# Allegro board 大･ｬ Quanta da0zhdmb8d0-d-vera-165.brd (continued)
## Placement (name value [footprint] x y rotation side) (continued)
TP278  *  [TP2050]  93.24 49.11 180 bottom
TP279  *  [TP2050]  127.83 40.72 180 bottom
TP280  *  [TP2050]  129.1 40.72 180 bottom
TP281  *  [TP2050]  130.95 40.72 180 bottom
TP282  *  [TP2050]  130.95 41.99 180 bottom
TP285  *  [TP2050]  89.76 39.28 180 bottom
TP286  *  [TP2050]  85.55 44.16 0 top
TP287  *  [TP2050]  85.12 46.72 0 top
U1  NAU88L25  [QFN32-5X5-5-33P-0_85H]  23.21 15.02 0 top
U3  MAX98357AETE+T*  [QFN16-3X3-5-17P-0_8H]  37.77 20.47 180 top
U4  AZC099-04S.R7G  [SOT23-6-2_8-95-6P]  12.26 67.29 0 top
U5  MAX98357AETE+T*  [QFN16-3X3-5-17P-0_8H]  32.64 20.5 180 top
U6  AZ1065-06F.R7G  [DFN10-4_1X2-8-11P]  17.62 29.24 270 bottom
U8  G5245AT11U  [SOT23-5-2_8-95-5P-G708]  43.4 55.41 90 top
U23  *RClamp0524P  [SON10-2_5X1-5-SMT]  16.15 43.06 90 bottom
U26  PS8203  [TQFN32-3X6-4-41P-0_8H]  21.1 44.97 90 top
U80  SKL_ULT  [BGA1356-INTEL-SKYLAKE-U]  123.83 57.1 90 bottom
U82  SLB9670  [QFN32-5X5-5-33P-SLB9645VQ]  58.92 57.77 270 top
U83  SLG4R41084  [QFN12-1_6X1_6-4]  150.36 21.49 180 top
U86  TPS22965  [SON8-2X2-5-9P]  174.97 23.53 0 top
U90  PI3USB9281CXWE  [QFN20-3X4-5-21P-0_55H]  21.94 68.36 0 top
U95  STM32F051CBU6TR  [QFN48-7X7-5-49P-0_65H]  34.14 49.59 180 top
U96  PI3USB30532  [QFN40-3X6-4-41P]  21.98 62.78 270 bottom
U97  AP21510FM-7  [DFN2018-6-1_8X2-5-7P]  17.75 58.27 0 top
U98  AP21510FM-7  [DFN2018-6-1_8X2-5-7P]  17.75 55.79 0 top
U108  *SN74LVC1G08DCKR  [SC70-2_1-65-5P]  23.46 20.73 180 bottom
U111  SN74LVC1G08DCKR  [SOT353-1-2_125-65-5P]  47.08 55.28 0 bottom
U123  74LVC1G74GT  [SON8-1_95X1-5]  85.82 25.56 90 bottom
U124  PJT7600  [SOT363-2_1-65-6P]  15.03 55.13 270 bottom
U126  PJT7600  [SOT363-2_1-65-6P]  14.88 54.9 270 top
U130  PJT7600  [SOT363-2_1-65-6P]  42 45.88 180 top
U132  *G923-330T1UF  [SOT23-5]  24.27 27.41 180 top
U133  TPD4E101DPWR  [SON4-0_8X0_8-48-5P-0_4H]  12.79 64.55 0 bottom
U135  SN74AHC1G08DCKR  [SOT353-1-2_125-65-5P]  95.47 89.57 0 top
U138  SN74LVC125APWR  [TSSOP14-6_4-65-TXB0104PWR]  94.32 78.28 180 top
UAP1008  SN74LVC1G08DCKR  [SOT353-1-2_125-65-5P]  71.32 57.31 180 top
UAP1012  W25Q128FVSIG_128Mb/16MB  [SOIC8-7_9-1_27-2_16H]  76.29 56.29 270 bottom
UCP4006  TMP432ADGSR  [TSSOP10-4_9-5]  90.74 17.04 270 bottom
UCP4007  *TMP431BDGKR  [MSOP8-4_9-65]  82.14 16.62 90 bottom
UCP4034  ESD_TPD4E05U06DQAR  [SON10-2_5X1-5-0_55H]  16.2 65.18 180 top
UCP4036  ESD_TPD4E05U06DQAR  [SON10-2_5X1-5-0_55H]  10.38 70.52 270 top
UPM3253  SPI_FLASH  [SOIC8-7_9-1_27]  94.33 30.89 90 bottom
USM2000  LPDDR3_SS_8G#1  [BGA178-SAMSUNG-K4E8E304EE]  168.58 74.11 0 bottom
USM2001  LPDDR3_SS_8G#1  [BGA178-SAMSUNG-K4E8E304EE]  152.33 85.34 0 bottom
USM2002  DC@LPDDR3_SS_8G#1  [BGA178-SAMSUNG-K4E8E304EE]  129.77 87.49 0 bottom
USM2003  DC@LPDDR3_SS_8G#1  [BGA178-SAMSUNG-K4E8E304EE]  111.04 87.49 0 bottom
USM2006  SDIN9DW4_16G  [BGA153-SANDISK-SDIN7DP4-16G]  59.93 48.33 180 bottom
X5  24MHz,30ppm  [XTL-3_2X2_5-2_2X1_6-0_9H]  123.66 35.64 0 bottom
X6  32.768KHz,20ppm  [XTL-3_2X1_5-2_5-0_8H]  105.5 78.11 0 bottom
X8  32.768KHz,20ppm  [XTL-3_2X1_5-2_5-0_8H]  78.96 51.09 180 top

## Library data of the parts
C1 C1C4 C1C7 C1C28 C1C29 C1C41-C1C45 C1C47 C1C48 C1C50 C1D8 C1D17 C1M4-C1M9 C1P4-C1P7 C2 C2B3 C2M1-C2M5 C3 C4 C7L11-C7L15 C8L3 C8L6 C8L7 C8L9 C8L11 C8L13-C8L20 C32 C35 C43 C51 C62-C65 C67 C72 C129-C133 C135-C137 C139 C141 C151 C153 C186 C187 C289 C291 C340 C341 C343 C344 C386 C437 C590 C783 C785 C789-C791 C827 C828 C831 C832 C842 C843 C849 C850 C867 C868 C870-C873 C887 C888 C893 C946-C948 C952 C968 C981-C984 C1009 C1024-C1033 C1080 C1087-C1089 C1102-C1107 C1109-C1116 C1136-C1142 C6001-C6005 CAP1020 CAP1022 CAP1024 CAP1073 CAP1079 CAP1101-CAP1103 CAP1108-CAP1110 CAP1115-CAP1117 CAP1122-CAP1124 CAP1129-CAP1131 CAP1136-CAP1138 CAP1141 CAP1142 CAP1147 CAP1148 CAP1150 CAP1152 CAP1155-CAP1157 CAP1159 CAP1161 CAP1162 CAP1164-CAP1169 CAP1171-CAP1174 CAP1176-CAP1179 CAP1181 CAP1183 CAP1184 CAP1186 CAP1187 CAP1189 CAP1191-CAP1194 CAP1196 CAP1197 CAP1199 CAP1201 CAP1203 CAP1204 CAP1206-CAP1208 CAP1210 CAP1211 CAP1213-CAP1215 CAP1217 CAP1218 CAP1220 CAP1221 CAP1223 CAP1224 CAP1226 CAP1227 CAP1229 CAP1231 CAP1232 CAP1234-CAP1236 CAP1240-CAP1245 CAP1247-CAP1250 CAP1252-CAP1262 CAP1264 CAP1265 CAP1267 CAP1268 CAP1270-CAP1272 CAP1274-CAP1313 CAP1316-CAP1321 CAP1422-CAP1439 CAP1441-CAP1452 CAP1456-CAP1465 CAP1467-CAP1495 CAP1498-CAP1500 CAP14466 CAP14472-CAP14483 CAP14490 CAP14491 CAP14493 CCP4019 CCP4089 CCP4090 CCP4092-CCP4094 CCP4156 CCP4157 CCP4166-CCP4169 CCP4195 CCP4196 CCP4198 CCP4215 CCP4216 CPM3428 CPM3432-CPM3440 CPM3479 CPM4346 CPM4429 CPM4431 CSM1017-CSM1030 CSM2029-CSM2043 CSM2097-CSM2111 CSM2129-CSM2131 CSM2133-CSM2142 CSM2156-CSM2160 CSM3132 EC2 EC3 PC1-PC3 PC8 PC9 PC12 PC14-PC27 PC46 PC301-PC310 PC1051 PC1142-PC1144 PC1146-PC1328 PC9091 PC9093-PC9123 = CAP NON-POL_BGM
CCP4197 PC4-PC7 PC10 PC11 PC9124 = CAP POL_BGM
CN2 JCP4056 = FFCFPC_30P_BGM
CN3 = FFCFPC_8P_BGM
CN4 J1P2 = FFCFPC_4P_BGM
CN8 = NGFF_79P_EKEY_FT_BGM
CN12 = HDMI_19P_BGM
CN17 = HOUSING_50P_2R_BGM
CPM4189 CPM4192 F2B1 F100 F104 JP3546 JP5076 JP5100 PR3-PR5 PR8 PR12-PR15 PR19 PR20 PR22 PR71-PR89 PR91-PR138 PR142-PR161 PR164-PR188 PR190 R1A1 R1A2 R1A4PD1 R1B26-R1B28 R1B30 R1B32 R1B33 R1C10 R1D4 R1D7 R1D9 R1D10 R1D13 R1D18 R1D19 R1D21 R1D22 R1M4 R1M5 R2B2 R41 R45-R49 R56 R59 R66 R88 R129-R134 R136 R138 R217 R338 R346 R529 R619 R679-R682 R687 R739 R788 R790 R851 R865 R866 R868-R870 R872-R874 R877 R879 R888-R892 R894-R896 R899 R900 R936 R979-R988 R999 R1000 R1022 R1023 R1040-R1047 R1049-R1054 R1056 R1064 R1075 R1082 R1084-R1086 R1097 R1106 R1113 R1117 R1120 R1124 R1129 R1131 R1134 R1138 R1141-R1144 R1157 R1162 R1163 R1168 R1169 R1178-R1182 R3491 R3499 R3503 R3550 R3587 R3591-R3594 R3596 R3597 R3604 R3608 R3609 R3611 R3614 R4434 R5004 R5009 R5020 R5027 R5037 R5038 R5041 R5042 R5049 R5050 R5057-R5060 R5073 R5079 R5081 R5084 R5085 R5087 R5088 R5090-R5092 R5094-R5097 R5100-R5102 R5106-R5110 R5116-R5118 R5123-R5150 R5152-R5155 R5157-R5160 R6001-R6003 R6006-R6009 RAP1000-RAP1005 RAP1008-RAP1011 RAP1013 RAP1014 RAP1016-RAP1019 RAP1021 RAP1023 RAP1025-RAP1035 RAP1044 RAP1046 RAP1047 RAP1049-RAP1055 RAP1061 RAP1062 RAP1064 RAP1067 RAP1072 RAP1075 RAP1077 RAP1078 RAP1081 RAP1087 RAP1088 RAP1091 RAP1322-RAP1324 RAP1327 RAP1328 RAP1330-RAP1333 RAP1335-RAP1337 RAP1343 RAP1344 RAP1387 RAP1407 RAP1408 RAP1412-RAP1414 RAP1423 RAP1424 RAP1430-RAP1434 RAP1436 RAP1438 RAP1440 RAP1450-RAP1453 RAP1455 RAP1458 RAP3020 RAP3021 RAP3023 RAP3040-RAP3049 RAP3051-RAP3054 RCP4021 RCP4029 RCP4037 RCP4074 RCP4160 RCP4162 RCP4184 RCP4186 RCP4190 RCP4191 RCP4193 RCP4194 RCP4219-RCP4221 RPM3123 RPM3337 RPM3426 RPM3427 RPM3429 RPM3452 RPM3453 RPM3457 RPM3458 RPM3465 RPM3467 RPM3468 RPM3470 RPM3472 RPM3473 RPM3475 RPM3476 RPM3558 RPM3562 RPM3573 RPM3576-RPM3581 RPM3589-RPM3592 RSM1012 RSM1014 RSM2007 RSM2008 RSM2075 RSM2076 RSM2112 RSM2113 RSM2143-RSM2152 RSM2155 = RES_BGM
CR5-CR9 CR15 CR16 CRPM3518 CRPM3519 D3 D41 = Schottky_DIODE_BGM
CRCP4008-CRCP4011 CRCP4014 CRCP4042 CRCP4043 U23 UCP4034 UCP4036 = TPD4E05U06DQAR_BGM
CRCP4028 PD1-PD3 = ZENER_DIODE_BGM
D4 D21 D46-D51 EC1 = TVS_DIODE_BGM
D60 D61 = AZ1045-04F_BGM
EU1B2 EUCP4040 = SN1408009RTER_BGM
EUPM3247 = MEC1322-LZY-C0_BGM
FB1 FB1C2 FB1C8 FB1C10 FB1C11 FB1D1 FB1D2 = BEAD_BGM
HOLE1 HOLE7 HOLE9 HOLE18 HOLE19 HOLE41-HOLE43 HOLE45 = 3x2_1.1
HOLE2 = 3x2_3.1
HOLE4 HOLE34-HOLE36 HOLE44 = 3x2_5.1
J1C1 = COMBOJACK_7P_BGM
J2 = USB3_13P_BGM
J8L1 = FFCFPC_40P_BGM
JCP4038 = USB3_1_24P_6fix_BGM
JP948-JP952 JP955 JP3507 JP3535-JP3539 JP3545 JP3547 JP3571 PR6 PR7 PR9-PR11 PR21 PR23-PR70 PR90 PR189 R1A3-R1A6 R1C5 R1C11 R1C12 R1D11 R1D12 R8A16 R11 R527 R771 R772 R956-R958 R960 R964 R977 R1002 R1048 R1071 R1074 R1076 R1104 R1105 R1109 R1115 R1116 R1118 R1119 R1139 R1158 R3493 R3501 R3502 R3504 R3526 R3534 R3535 R3571 R3603 R3620 R5010 R5018 R5026 R5039 R5040 R5043 R5051 R5063 R5066 R5068 R5072 R5078 R5080 R5086 R5093 R5098 R5099 R5103 R5104 R5115 R5151 RAP1089 RAP1090 RAP1325 RAP1326 RAP1351 RAP1352 RAP1360 RAP1364 RAP1376 RAP1377 RAP1381-RAP1386 RAP1405 RAP1406 RAP1409 RAP1410 RAP1422 RAP1428 RAP1429 RAP1457 RAP1459 RCP4072 RCP4216 RPM3282-RPM3298 RPM3305 RPM3309 RPM3312 RPM3314-RPM3317 RPM3324 RPM3326-RPM3329 RPM3331 RPM3333 RPM3338 RPM3431 RPM3455 RPM3460-RPM3463 = SHORTPAD_BGM
L10-L13 L16-L19 LCP4022 LCP4041 LCP4042 = BW_BGM
L15 PL4-PL7 = INDUCTOR_BGM
LED1 LED2 = LED_3P_BLU_ORG_CA_BGM
MR1 = HALL_IC_3P_BGM
PD4 = BAT54C_BGM
PJ2 = Header_8P_BGM
PL1-PL3 PL8-PL10 = INDUCTOR_BGM_0
PQ1 = MOS-P_8P_BGM
PQ2 PQ3 = CSD87330Q3D_BGM
PQ129 Q111-Q114 Q127 Q129 Q135 Q136 Q139 QAP1009 QCP4007 QCP4112 QPM3251 QPM3360 QPM3362 QPM3371-QPM3374 QPM3382-QPM3384 QPM3387-QPM3391 = MOS-N_3P_ESD_BGM
PQ130 = MOS-N_3P_BGM
PR1 PR2 RPM3310 RPM3323 = R_Current_SEN_BGM
PR139-PR141 PR162 PR163 = Thermistor_BGM_0
PU1 = TMP708_BGM
PU2 = FPF2495UCX_BGM
PU3 = NX20P5090UK_BGM
PU4 = ISL9237HRZ-T_BGM
PU5 = ISL95857HRTZ-T_40P_BGM
PU6-PU8 = SIC532CD-T1-GE3_13P_BGM
PU9 = ISL95808HRZ-T_BGM
PU10 = SIZ340DT-T1-GE3_10P_BGM
PU11 PU15 = SN74AUP1G97DCKR_BGM
PU12-PU14 PU16 PU19 PU20 = SLG5NT1477VTR_7P_BGM
PU17 PU18 PU21-PU23 = SLG7NT402VTR_6P_BGM_0
PU50 U108 U111 U135 UAP1008 = Logic_AND_BGM
PU51 = AOZ1331DI_BGM
PU3044 PU3045 PU3047 PU3048 = CSD87381P_5P_BGM
PU3254 = TPS650830ZCGR_159P_BGM
Q5 QCP4009-QCP4011 = NPN_BGM
Q10 = AP2331SA-7-01_BGM
Q105 = MOS-P_3P_BGM
Q109 Q110 Q121 Q125 = DTC144EU_BGM
Q137 = MOS-N_Dual_6P_ESD_BGM
SW1 = SW_6P_BGM
TP17 TP18 TP20-TP24 TP33 TP34 TP39 TP48 TP49 TP51 TP52 TP57 TP61 TP63 TP71 TP75-TP91 TP98 TP100-TP102 TP106-TP118 TP120 TP125 TP127 TP131 TP136-TP143 TP146-TP148 TP159 TP160 TP165 TP167-TP172 TP177-TP180 TP189-TP191 TP202 TP204 TP211-TP213 TP221-TP225 TP230-TP233 TP238 TP242-TP246 TP249-TP269 TP271-TP282 TP285-TP287 = TP_BGM
U1 = NAU88L25YGB_BGM
U3 U5 = MAX98357AETE+T_BGM
U4 = AZC099-04S.R_BGM
U6 = AZ1065-06F.R7G_10P-BGM
U8 = G5245AT11U_BGM
U26 = PS8203TQFN32GTR-A3_BGM
U80 = PD7H_SKL_ULT_S
U82 = SLB9670VQ1.2 FW6.40GOOG_BGM
U83 = SLG4R41084_BGM
U86 = TPS22965DSGR_BGM
U90 = PI3USB9281CXWE_BGM
U95 = STM32F051C8U6TR_32P_BGM
U96 = PI3USB30532ZLE_BGM
U97 U98 = AP21510FM-7_BGM
U123 = 74LVC1G74GT_BGM
U124 U126 U130 = MOS-NP-6P_ESD_BGM
U132 = G923-330T1UF_BGM
U133 = TPD4E101DPWR_BGM
U138 = SN74LVC125APWR_14P_BGM
UAP1012 UPM3253 = W25Q80BWSSIG_BGM
UCP4006 = TMP432ADGSR_BGM
UCP4007 = TMP431BDGKR_BGM
USM2000-USM2003 = LPDDR3_178P_BGM
USM2006 = EMMC_153P_BGM
X5 = CRYSTAL_4P_BGM
X6 X8 = CRYSTAL_2P_BGM

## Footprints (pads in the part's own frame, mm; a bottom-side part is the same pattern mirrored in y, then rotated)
50271-0040N-V01-4P-L
  rect 0.787x1.6 smd: 1(-1.875,2.9) 2(-0.625,2.9) 3(0.625,2.9) 4(1.875,2.9)
  rect 2.108x2.997 smd: 5(-4.425,0) 6(4.425,0)
50458-00801-V02-8P-L
  rect 0.559x1.295 smd: 1(-7,5.025) 2(-5,5.025) 3(-3,5.025) 4(-1,5.025) 5(1,5.025) 6(3,5.025) 7(5,5.025) 8(7,5.025)
  rect 1.295x2.057 smd: 9(-10.1,0) 10(10.1,0)
51619-0300N-001-30P-L
  rect 0.305x1.295 smd: 1(-7.25,2.8) 2(-6.75,2.8) 3(-6.25,2.8) 4(-5.75,2.8) 5(-5.25,2.8) 6(-4.75,2.8) 7(-4.25,2.8) 8(-3.75,2.8) 9(-3.25,2.8) 10(-2.75,2.8) 11(-2.25,2.8) 12(-1.75,2.8) 13(-1.25,2.8) 14(-0.75,2.8) 15(-0.25,2.8) 16(0.25,2.8) 17(0.75,2.8) 18(1.25,2.8) 19(1.75,2.8) 20(2.25,2.8) 21(2.75,2.8) 22(3.25,2.8) 23(3.75,2.8) 24(4.25,2.8) 25(4.75,2.8) 26(5.25,2.8) 27(5.75,2.8) 28(6.25,2.8) 29(6.75,2.8) 30(7.25,2.8)
  rect 1.803x1.397 smd: 31(-8.9,0) 32(8.9,0)
51646-0300N-V01-30P-L
  rect 0.406x1.499 smd: 1(-11.6,1.6) 2(-10.8,1.6) 3(-10,1.6) 4(-9.2,1.6) 5(-8.4,1.6) 6(-7.6,1.6) 7(-6.8,1.6) 8(-6,1.6) 9(-5.2,1.6) 10(-4.4,1.6) 11(-3.6,1.6) 12(-2.8,1.6) 13(-2,1.6) 14(-1.2,1.6) 15(-0.4,1.6) 16(0.4,1.6) 17(1.2,1.6) 18(2,1.6) 19(2.8,1.6) 20(3.6,1.6) 21(4.4,1.6) 22(5.2,1.6) 23(6,1.6) 24(6.8,1.6) 25(7.6,1.6) 26(8.4,1.6) 27(9.2,1.6) 28(10,1.6) 29(10.8,1.6) 30(11.6,1.6)
  rect 2.388x2.388 smd: 31(-14.65,0.2) 32(14.65,0.2)
51653-0080N-001-8P-L
  rect 0.508x1.295 smd: 1(-3.5,2.8) 2(-2.5,2.8) 3(-1.5,2.8) 4(-0.5,2.8) 5(0.5,2.8) 6(1.5,2.8) 7(2.5,2.8) 8(3.5,2.8)
  rect 1.803x1.397 smd: 9(-5.65,0) 10(5.65,0)
196522-40041-3-40P-LDH
  rect 0.305x1.295 smd: 1(-9.75,5.65) 2(-9.25,5.65) 3(-8.75,5.65) 4(-8.25,5.65) 5(-7.75,5.65) 6(-7.25,5.65) 7(-6.75,5.65) 8(-6.25,5.65) 9(-5.75,5.65) 10(-5.25,5.65) 11(-4.75,5.65) 12(-4.25,5.65) 13(-3.75,5.65) 14(-3.25,5.65) 15(-2.75,5.65) 16(-2.25,5.65) 17(-1.75,5.65) 18(-1.25,5.65) 19(-0.75,5.65) 20(-0.25,5.65) 21(0.25,5.65) 22(0.75,5.65) 23(1.25,5.65) 24(1.75,5.65) 25(2.25,5.65) 26(2.75,5.65) 27(3.25,5.65) 28(3.75,5.65) 29(4.25,5.65) 30(4.75,5.65) 31(5.25,5.65) 32(5.75,5.65) 33(6.25,5.65) 34(6.75,5.65) 35(7.25,5.65) 36(7.75,5.65) 37(8.25,5.65) 38(8.75,5.65) 39(9.25,5.65) 40(9.75,5.65)
  rect 1.803x2.21 smd: 41(-11.9,0) 42(11.9,0)
AUDIO-2SJ3080-108111F-6P
  oval 0.991x1.803 hole 0.61x1.397: 1(-4.85,7.225) 2(4.7,1.725) 3(-4.85,-0.575) 4(4.7,-1.175) 5(4.7,7.225) 6(4.7,4.475) 7(-4.85,3.125)
AXK750147G-50P-LDV
  rect 0.406x1.092 smd: 1(-4.885,-2.3) 2(-4.885,2.3) 49(4.885,-2.3) 50(4.885,2.3)
  rect 0.203x1.092 smd: 3(-4.4,-2.3) 4(-4.4,2.3) 5(-4,-2.3) 6(-4,2.3) 7(-3.6,-2.3) 8(-3.6,2.3) 9(-3.2,-2.3) 10(-3.2,2.3) 11(-2.8,-2.3) 12(-2.8,2.3) 13(-2.4,-2.3) 14(-2.4,2.3) 15(-2,-2.3) 16(-2,2.3) 17(-1.6,-2.3) 18(-1.6,2.3) 19(-1.2,-2.3) 20(-1.2,2.3) 21(-0.8,-2.3) 22(-0.8,2.3) 23(-0.4,-2.3) 24(-0.4,2.3) 25(0,-2.3) 26(0,2.3) 27(0.4,-2.3) 28(0.4,2.3) 29(0.8,-2.3) 30(0.8,2.3) 31(1.2,-2.3) 32(1.2,2.3) 33(1.6,-2.3) 34(1.6,2.3) 35(2,-2.3) 36(2,2.3) 37(2.4,-2.3) 38(2.4,2.3) 39(2.8,-2.3) 40(2.8,2.3) 41(3.2,-2.3) 42(3.2,2.3) 43(3.6,-2.3) 44(3.6,2.3) 45(4,-2.3) 46(4,2.3) 47(4.4,-2.3) 48(4.4,2.3)
BGA9-FAIRCHILD-FPF2495UCX
  round 0.203 smd: A1(-0.4,-0.4) A2(-0.4,0) A3(-0.4,0.4) B1(0,-0.4) B2(0,0) B3(0,0.4) C1(0.4,-0.4) C2(0.4,0) C3(0.4,0.4)
BGA15-NXP-NX20P5090UK
  round 0.254 smd: A1(-0.5,-1) A2(0,-1) A3(0.5,-1) B1(-0.5,-0.5) B2(0,-0.5) B3(0.5,-0.5) C1(-0.5,0) C2(0,0) C3(0.5,0) D1(-0.5,0.5) D2(0,0.5) D3(0.5,0.5) E1(-0.5,1) E2(0,1) E3(0.5,1)
BGA153-SANDISK-SDIN7DP4-16G
  round 0.254 smd: A1(-3.25,-3.25) A2(-3.25,-2.75) A3(-3.25,-2.25) A4(-3.25,-1.75) A5(-3.25,-1.25) A6(-3.25,-0.75) A7(-3.25,-0.25) A8(-3.25,0.25) A9(-3.25,0.75) A10(-3.25,1.25) A11(-3.25,1.75) A12(-3.25,2.25) A13(-3.25,2.75) A14(-3.25,3.25) B1(-2.75,-3.25) B2(-2.75,-2.75) B3(-2.75,-2.25) B4(-2.75,-1.75) B5(-2.75,-1.25) B6(-2.75,-0.75) B7(-2.75,-0.25) B8(-2.75,0.25) B9(-2.75,0.75) B10(-2.75,1.25) B11(-2.75,1.75) B12(-2.75,2.25) B13(-2.75,2.75) B14(-2.75,3.25) C1(-2.25,-3.25) C2(-2.25,-2.75) C3(-2.25,-2.25) C4(-2.25,-1.75) C5(-2.25,-1.25) C6(-2.25,-0.75) C7(-2.25,-0.25) C8(-2.25,0.25) C9(-2.25,0.75) C10(-2.25,1.25) C11(-2.25,1.75) C12(-2.25,2.25) C13(-2.25,2.75) C14(-2.25,3.25) D1(-1.75,-3.25) D2(-1.75,-2.75) D3(-1.75,-2.25) D4(-1.75,-1.75) D12(-1.75,2.25) D13(-1.75,2.75) D14(-1.75,3.25) E1(-1.25,-3.25) E2(-1.25,-2.75) E3(-1.25,-2.25) E5(-1.25,-1.25) E6(-1.25,-0.75) E7(-1.25,-0.25) E8(-1.25,0.25) E9(-1.25,0.75) E10(-1.25,1.25) E12(-1.25,2.25) E13(-1.25,2.75) E14(-1.25,3.25) F1(-0.75,-3.25) F2(-0.75,-2.75) F3(-0.75,-2.25) F5(-0.75,-1.25) F10(-0.75,1.25) F12(-0.75,2.25) F13(-0.75,2.75) F14(-0.75,3.25) G1(-0.25,-3.25) G2(-0.25,-2.75) G3(-0.25,-2.25) G5(-0.25,-1.25) G10(-0.25,1.25) G12(-0.25,2.25) G13(-0.25,2.75) G14(-0.25,3.25) H1(0.25,-3.25) H2(0.25,-2.75) H3(0.25,-2.25) H5(0.25,-1.25) H10(0.25,1.25) H12(0.25,2.25) H13(0.25,2.75) H14(0.25,3.25) J1(0.75,-3.25) J2(0.75,-2.75) J3(0.75,-2.25) J5(0.75,-1.25) J10(0.75,1.25) J12(0.75,2.25) J13(0.75,2.75) J14(0.75,3.25) K1(1.25,-3.25) K2(1.25,-2.75) K3(1.25,-2.25) K5(1.25,-1.25) K6(1.25,-0.75) K7(1.25,-0.25) K8(1.25,0.25) K9(1.25,0.75) K10(1.25,1.25) K12(1.25,2.25) K13(1.25,2.75) K14(1.25,3.25) L1(1.75,-3.25) L2(1.75,-2.75) L3(1.75,-2.25) L12(1.75,2.25) L13(1.75,2.75) L14(1.75,3.25) M1(2.25,-3.25) M2(2.25,-2.75) M3(2.25,-2.25) M4(2.25,-1.75) M5(2.25,-1.25) M6(2.25,-0.75) M7(2.25,-0.25) M8(2.25,0.25) M9(2.25,0.75) M10(2.25,1.25) M11(2.25,1.75) M12(2.25,2.25) M13(2.25,2.75) M14(2.25,3.25) N1(2.75,-3.25) N2(2.75,-2.75) N3(2.75,-2.25) N4(2.75,-1.75) N5(2.75,-1.25) N6(2.75,-0.75) N7(2.75,-0.25) N8(2.75,0.25) N9(2.75,0.75) N10(2.75,1.25) N11(2.75,1.75) N12(2.75,2.25) N13(2.75,2.75) N14(2.75,3.25) P1(3.25,-3.25) P2(3.25,-2.75) P3(3.25,-2.25) P4(3.25,-1.75) P5(3.25,-1.25) P6(3.25,-0.75) P7(3.25,-0.25) P8(3.25,0.25) P9(3.25,0.75) P10(3.25,1.25) P11(3.25,1.75) P12(3.25,2.25) P13(3.25,2.75) P14(3.25,3.25)
BGA159-TEXAS-TPS650830
  round 0.254 smd: A1(-3.75,-3.75) A2(-3.75,-3.25) A3(-3.75,-2.75) A4(-3.75,-2.25) A5(-3.75,-1.75) A6(-3.75,-1.25) A7(-3.75,-0.75) A8(-3.75,-0.25) A9(-3.75,0.25) A10(-3.75,0.75) A11(-3.75,1.25) A12(-3.75,1.75) A13(-3.75,2.25) A14(-3.75,2.75) A15(-3.75,3.25) A16(-3.75,3.75) B1(-3.25,-3.75) B2(-3.25,-3.25) B5(-3.25,-1.75) B7(-3.25,-0.75) B8(-3.25,-0.25) B9(-3.25,0.25) B11(-3.25,1.25) B13(-3.25,2.25) B15(-3.25,3.25) B16(-3.25,3.75) C1(-2.75,-3.75) C2(-2.75,-3.25) C4(-2.75,-2.25) C6(-2.75,-1.25) C8(-2.75,-0.25) C10(-2.75,0.75) C12(-2.75,1.75) C14(-2.75,2.75) C16(-2.75,3.75) D1(-2.25,-3.75) D3(-2.25,-2.75) D5(-2.25,-1.75) D7(-2.25,-0.75) D9(-2.25,0.25) D11(-2.25,1.25) D13(-2.25,2.25) D15(-2.25,3.25) D16(-2.25,3.75) E1(-1.75,-3.75) E4(-1.75,-2.25) E6(-1.75,-1.25) E8(-1.75,-0.25) E10(-1.75,0.75) E12(-1.75,1.75) E14(-1.75,2.75) E16(-1.75,3.75) F1(-1.25,-3.75) F3(-1.25,-2.75) F5(-1.25,-1.75) F7(-1.25,-0.75) F9(-1.25,0.25) F11(-1.25,1.25) F13(-1.25,2.25) F15(-1.25,3.25) F16(-1.25,3.75) G1(-0.75,-3.75) G2(-0.75,-3.25) G4(-0.75,-2.25) G6(-0.75,-1.25) G8(-0.75,-0.25) G10(-0.75,0.75) G12(-0.75,1.75) G14(-0.75,2.75) G16(-0.75,3.75) H1(-0.25,-3.75) H3(-0.25,-2.75) H5(-0.25,-1.75) H7(-0.25,-0.75) H9(-0.25,0.25) H11(-0.25,1.25) H13(-0.25,2.25) H15(-0.25,3.25) H16(-0.25,3.75) J1(0.25,-3.75) J2(0.25,-3.25) J4(0.25,-2.25) J6(0.25,-1.25) J8(0.25,-0.25) J10(0.25,0.75) J12(0.25,1.75) J14(0.25,2.75) J15(0.25,3.25) J16(0.25,3.75) K1(0.75,-3.75) K3(0.75,-2.75) K5(0.75,-1.75) K7(0.75,-0.75) K9(0.75,0.25) K11(0.75,1.25) K13(0.75,2.25) K15(0.75,3.25) K16(0.75,3.75) L1(1.25,-3.75) L2(1.25,-3.25) L4(1.25,-2.25) L6(1.25,-1.25) L8(1.25,-0.25) L10(1.25,0.75) L12(1.25,1.75) L14(1.25,2.75) L16(1.25,3.75) M1(1.75,-3.75) M3(1.75,-2.75) M5(1.75,-1.75) M7(1.75,-0.75) M9(1.75,0.25) M11(1.75,1.25) M13(1.75,2.25) M15(1.75,3.25) M16(1.75,3.75) N1(2.25,-3.75) N2(2.25,-3.25) N4(2.25,-2.25) N6(2.25,-1.25) N8(2.25,-0.25) N10(2.25,0.75) N12(2.25,1.75) N14(2.25,2.75) N16(2.25,3.75) P1(2.75,-3.75) P3(2.75,-2.75) P5(2.75,-1.75) P7(2.75,-0.75) P9(2.75,0.25) P11(2.75,1.25) P13(2.75,2.25) P16(2.75,3.75) R1(3.25,-3.75) R2(3.25,-3.25) R4(3.25,-2.25) R6(3.25,-1.25) R8(3.25,-0.25) R10(3.25,0.75) R12(3.25,1.75) R14(3.25,2.75) R15(3.25,3.25) R16(3.25,3.75) T1(3.75,-3.75) T2(3.75,-3.25) T3(3.75,-2.75) T4(3.75,-2.25) T5(3.75,-1.75) T6(3.75,-1.25) T7(3.75,-0.75) T8(3.75,-0.25) T9(3.75,0.25) T10(3.75,0.75) T11(3.75,1.25) T12(3.75,1.75) T13(3.75,2.25) T14(3.75,2.75) T15(3.75,3.25) T16(3.75,3.75)
BGA178-SAMSUNG-K4E8E304EE
  round 0.254 smd: A1(-5.2,-4.8) A2(-5.2,-4) A3(-5.2,-3.2) A4(-5.2,-2.4) A5(-5.2,-1.6) A6(-5.2,-0.8) A8(-5.2,0.8) A9(-5.2,1.6) A10(-5.2,2.4) A11(-5.2,3.2) A12(-5.2,4) A13(-5.2,4.8) B1(-4.55,-4.8) B2(-4.55,-4) B3(-4.55,-3.2) B4(-4.55,-2.4) B5(-4.55,-1.6) B6(-4.55,-0.8) B8(-4.55,0.8) B9(-4.55,1.6) B10(-4.55,2.4) B11(-4.55,3.2) B12(-4.55,4) B13(-4.55,4.8) C2(-3.9,-4) C3(-3.9,-3.2) C4(-3.9,-2.4) C5(-3.9,-1.6) C6(-3.9,-0.8) C8(-3.9,0.8) C9(-3.9,1.6) C10(-3.9,2.4) C11(-3.9,3.2) C12(-3.9,4) D2(-3.25,-4) D3(-3.25,-3.2) D4(-3.25,-2.4) D5(-3.25,-1.6) D6(-3.25,-0.8) D8(-3.25,0.8) D9(-3.25,1.6) D10(-3.25,2.4) D11(-3.25,3.2) D12(-3.25,4) E2(-2.6,-4) E3(-2.6,-3.2) E4(-2.6,-2.4) E5(-2.6,-1.6) E6(-2.6,-0.8) E8(-2.6,0.8) E9(-2.6,1.6) E10(-2.6,2.4) E11(-2.6,3.2) E12(-2.6,4) F2(-1.95,-4) F3(-1.95,-3.2) F4(-1.95,-2.4) F5(-1.95,-1.6) F6(-1.95,-0.8) F8(-1.95,0.8) F9(-1.95,1.6) F10(-1.95,2.4) F11(-1.95,3.2) F12(-1.95,4) G2(-1.3,-4) G3(-1.3,-3.2) G4(-1.3,-2.4) G5(-1.3,-1.6) G6(-1.3,-0.8) G8(-1.3,0.8) G9(-1.3,1.6) G10(-1.3,2.4) G11(-1.3,3.2) G12(-1.3,4) H2(-0.65,-4) H3(-0.65,-3.2) H4(-0.65,-2.4) H5(-0.65,-1.6) H6(-0.65,-0.8) H8(-0.65,0.8) H9(-0.65,1.6) H10(-0.65,2.4) H11(-0.65,3.2) H12(-0.65,4) J2(0,-4) J3(0,-3.2) J4(0,-2.4) J5(0,-1.6) J6(0,-0.8) J8(0,0.8) J9(0,1.6) J10(0,2.4) J11(0,3.2) J12(0,4) K2(0.65,-4) K3(0.65,-3.2) K4(0.65,-2.4) K5(0.65,-1.6) K6(0.65,-0.8) K8(0.65,0.8) K9(0.65,1.6) K10(0.65,2.4) K11(0.65,3.2) K12(0.65,4) L2(1.3,-4) L3(1.3,-3.2) L4(1.3,-2.4) L5(1.3,-1.6) L6(1.3,-0.8) L8(1.3,0.8) L9(1.3,1.6) L10(1.3,2.4) L11(1.3,3.2) L12(1.3,4) M2(1.95,-4) M3(1.95,-3.2) M4(1.95,-2.4) M5(1.95,-1.6) M6(1.95,-0.8) M8(1.95,0.8) M9(1.95,1.6) M10(1.95,2.4) M11(1.95,3.2) M12(1.95,4) N2(2.6,-4) N3(2.6,-3.2) N4(2.6,-2.4) N5(2.6,-1.6) N6(2.6,-0.8) N8(2.6,0.8) N9(2.6,1.6) N10(2.6,2.4) N11(2.6,3.2) N12(2.6,4) P2(3.25,-4) P3(3.25,-3.2) P4(3.25,-2.4) P5(3.25,-1.6) P6(3.25,-0.8) P8(3.25,0.8) P9(3.25,1.6) P10(3.25,2.4) P11(3.25,3.2) P12(3.25,4) R2(3.9,-4) R3(3.9,-3.2) R4(3.9,-2.4) R5(3.9,-1.6) R6(3.9,-0.8) R8(3.9,0.8) R9(3.9,1.6) R10(3.9,2.4) R11(3.9,3.2) R12(3.9,4) T1(4.55,-4.8) T2(4.55,-4) T3(4.55,-3.2) T4(4.55,-2.4) T5(4.55,-1.6) T6(4.55,-0.8) T8(4.55,0.8) T9(4.55,1.6) T10(4.55,2.4) T11(4.55,3.2) T12(4.55,4) T13(4.55,4.8) U1(5.2,-4.8) U2(5.2,-4) U3(5.2,-3.2) U4(5.2,-2.4) U5(5.2,-1.6) U6(5.2,-0.8) U8(5.2,0.8) U9(5.2,1.6) U10(5.2,2.4) U11(5.2,3.2) U12(5.2,4) U13(5.2,4.8)
BGA1356-INTEL-SKYLAKE-U
  round 0.356 smd: A3(-11.314,-19.349) A70(-11.314,19.852) B2(-10.832,-19.832) B71(-10.852,20.314) BA1(10.852,-20.314) BA71(10.852,20.314) BB2(11.314,-19.852) BB70(11.314,19.852) C1(-10.349,-20.314)
  round 0.33 smd: A4(-11.314,-18.699) A69(-11.314,19.202) AY1(10.202,-20.314) AY71(10.202,20.314) B3(-10.679,-19.197) B70(-10.685,19.685) BA2(10.685,-19.685) BA70(10.685,19.685) BB3(11.314,-19.202) BB69(11.314,19.202) C2(-10.197,-19.679) C71(-10.202,20.314) D1(-9.699,-20.314)
  round 0.305 smd: A5(-11.314,-18.048) A68(-11.314,18.552) AA2(-0.511,-19.339) AA4(-0.511,-18.363) AA63(-0.596,15.112) AA64(-0.596,15.763) AA65(-0.596,16.413) AA66(-0.596,17.063) AA67(-0.596,17.713) AA68(-0.596,18.364) AA69(-0.596,19.014) AA70(-0.596,19.664) AA71(-0.596,20.314) AB4(0.152,-18.363) AB6(-0.133,-17.585) AB7(-0.133,-16.935) AB8(-0.133,-16.285) AB9(-0.133,-15.635) AB10(-0.133,-14.984) AB11(-0.133,-14.334) AB12(-0.133,-13.684) AB13(-0.133,-13.034) AB15(-0.009,-12.188) AB16(-0.009,-11.538) AB17(-0.009,-10.888) AB18(-0.009,-10.237) AB19(-0.009,-9.587) AB20(-0.009,-8.937) AB21(-0.009,-8.287) AB62(-0.138,14.644) AC3(0.815,-18.689) AC63(0.319,15.112) AC64(0.319,15.763) AC65(0.319,16.413) AC66(0.319,17.063) AC67(0.319,17.713) AC68(0.319,18.364) AC69(0.319,19.014) AC70(0.319,19.664) AC71(0.319,20.314) AD4(1.478,-18.363) AD6(0.934,-17.585) AD7(0.934,-16.935) AD8(0.934,-16.285) AD9(0.934,-15.635) AD10(0.934,-14.984) AD11(0.934,-14.334) AD12(0.934,-13.684) AD13(0.934,-13.034) AD15(0.829,-12.188) AD16(0.829,-11.538) AD17(0.829,-10.888) AD18(0.829,-10.237) AD19(0.829,-9.587) AD20(0.829,-8.937) AD21(0.829,-8.287) AD62(0.776,14.644) AE62(1.69,14.644) AE63(1.233,15.112) AE64(1.233,15.763) AE65(1.233,16.413) AE66(1.233,17.063) AE67(1.233,17.713) AE68(1.233,18.364) AE69(1.233,19.014) AF2(2.141,-19.339) AF4(2.141,-18.363) AF6(2.001,-17.585) AF7(2.001,-16.935) AF8(2.001,-16.285) AF9(2.001,-15.635) AF10(2.001,-14.984) AF11(2.001,-14.334) AF12(2.001,-13.684) AF13(2.001,-13.034) AF15(1.668,-12.188) AF16(1.668,-11.538) AF17(1.668,-10.888) AF18(1.668,-10.237) AF19(1.668,-9.587) AF20(1.668,-8.937) AF21(1.668,-8.287) AF63(2.148,15.112) AF64(2.148,15.763) AF65(2.148,16.413) AF66(2.148,17.063) AF67(2.148,17.713) AF68(1.939,18.364) AF69(1.939,19.014) AG4(2.804,-18.363) AG15(2.506,-12.188) AG16(2.506,-11.538) AG17(2.506,-10.888) AG18(2.506,-10.237) AG19(2.506,-9.587) AG20(2.506,-8.937) AG21(2.506,-8.287) AG62(2.605,14.644) AG69(2.602,18.689) AH3(3.467,-18.689) AH6(3.067,-17.585) AH7(3.067,-16.935) AH8(3.067,-16.285) AH9(3.067,-15.635) AH10(3.067,-14.984) AH11(3.067,-14.334) AH12(3.067,-13.684) AH13(3.067,-13.034) AH63(3.062,15.112) AH64(3.062,15.763) AH65(3.062,16.413) AH66(3.062,17.063) AH67(3.062,17.713) AJ4(4.13,-18.363) AJ15(3.344,-12.188) AJ16(3.344,-11.538) AJ17(3.344,-10.888) AJ18(3.344,-10.237) AJ19(3.344,-9.587) AJ20(3.344,-8.937) AJ21(3.344,-8.287) AJ62(3.519,14.644) AK6(4.007,-17.585) AK7(4.007,-16.935) AK8(4.007,-16.285) AK9(4.007,-15.635) AK10(4.007,-14.984) AK11(4.007,-14.334) AK12(4.007,-13.684) AK13(4.007,-13.034) AK15(4.182,-12.188) AK16(4.182,-11.538) AK17(4.182,-10.888) AK18(4.182,-10.237) AK19(4.182,-9.587) AK20(4.182,-8.937) AK21(4.182,-8.287) AK22(4.009,-7.596) AK23(4.009,-6.681) AK25(4.009,-5.767) AK27(4.009,-4.852) AK28(4.009,-3.938) AK30(4.009,-3.024) AK32(4.009,-2.109) AK33(4.009,-1.195) AK35(4.009,-0.28) AK37(4.009,0.634) AK38(4.009,1.548) AK40(4.009,2.463) AK42(4.009,3.377) AK43(4.009,4.292) AK45(4.009,5.206) AK46(4.009,6.12) AK48(4.009,7.035) AK50(4.009,7.949) AK52(4.009,8.864) AK53(4.009,9.778) AK55(4.009,10.692) AK56(4.009,11.607) AK58(4.009,12.521) AK60(4.009,13.436) AK62(4.144,14.46) AK63(3.976,15.112) AK64(3.976,15.763) AK65(3.976,16.413) AK66(3.976,17.063) AK67(3.976,17.713) AK68(3.829,18.364) AK69(3.829,19.339) AL2(4.793,-19.339) AL4(4.793,-18.363) AL23(4.474,-7.138) AL25(4.474,-6.224) AL27(4.474,-5.31) AL28(4.474,-4.395) AL30(4.474,-3.481) AL32(4.474,-2.566) AL33(4.474,-1.652) AL35(4.474,-0.738) AL37(4.474,0.177) AL38(4.474,1.091) AL40(4.474,2.006) AL42(4.474,2.92) AL43(4.474,3.834) AL45(4.474,4.749) AL46(4.474,5.663) AL48(4.474,6.578) AL50(4.474,7.492) AL52(4.474,8.406) AL53(4.474,9.321) AL55(4.474,10.235) AL56(4.474,11.15) AL58(4.474,12.064) AL60(4.474,12.978) AL61(4.474,13.893) AL63(4.845,15.112) AL64(4.845,15.763) AL65(4.845,16.413) AL66(4.845,17.063) AM4(5.456,-18.363) AM5(4.946,-17.654) AM7(4.946,-16.74) AM8(4.946,-15.825) AM10(4.946,-14.911) AM11(4.946,-13.996) AM13(4.946,-13.082) AM15(4.946,-12.168) AM16(4.946,-11.253) AM18(4.946,-10.339) AM20(4.946,-9.424) AM21(4.946,-8.51) AM22(4.946,-7.596) AM23(4.946,-6.681) AM25(4.946,-5.767) AM27(4.946,-4.852) AM28(4.946,-3.938) AM30(4.946,-3.024) AM32(4.946,-2.109) AM33(4.946,-1.195) AM35(4.946,-0.28) AM37(4.946,0.634) AM38(4.946,1.548) AM40(4.946,2.463) AM42(4.946,3.377) AM43(4.946,4.292) AM45(4.946,5.206) AM46(4.946,6.12) AM48(4.946,7.035) AM50(4.946,7.949) AM52(4.946,8.864) AM53(4.946,9.778) AM55(4.946,10.692) AM56(4.946,11.607) AM58(4.946,12.521) AM60(4.946,13.436) AM61(4.946,14.35) AM68(5.056,18.039) AM69(5.056,18.689) AN3(6.119,-18.689) AN5(5.597,-17.654) AN7(5.597,-16.74) AN8(5.597,-15.825) AN10(5.597,-14.911) AN11(5.597,-13.996) AN13(5.597,-13.082) AN15(5.597,-12.168) AN16(5.597,-11.253) AN18(5.597,-10.339) AN20(5.597,-9.424) AN21(5.597,-8.51) AN22(5.597,-7.596) AN23(5.597,-6.681) AN25(5.597,-5.767) AN27(5.597,-4.852) AN28(5.597,-3.938) AN30(5.597,-3.024) AN32(5.597,-2.109) AN33(5.597,-1.195) AN35(5.597,-0.28) AN37(5.597,0.634) AN38(5.597,1.548) AN40(5.597,2.463) AN42(5.597,3.377) AN43(5.597,4.292) AN45(5.597,5.206) AN46(5.597,6.12) AN48(5.597,7.035) AN50(5.597,7.949) AN52(5.597,8.864) AN53(5.597,9.778) AN55(5.597,10.692) AN56(5.597,11.607) AN58(5.597,12.521) AN60(5.597,13.436) AN61(5.597,14.35) AN63(5.597,15.264) AN65(5.597,16.179) AN66(5.597,17.093) AN68(5.719,18.364) AN69(5.719,19.014) AP4(6.782,-18.363) AP5(6.247,-17.654) AP7(6.247,-16.74) AP8(6.247,-15.825) AP10(6.247,-14.911) AP11(6.247,-13.996) AP13(6.247,-13.082) AP15(6.247,-12.168) AP16(6.247,-11.253) AP18(6.247,-10.339) AP20(6.247,-9.424) AP21(6.247,-8.51) AP22(6.247,-7.596) AP23(6.247,-6.681) AP25(6.247,-5.767) AP27(6.247,-4.852) AP28(6.247,-3.938) AP30(6.247,-3.024) AP32(6.247,-2.109) AP33(6.247,-1.195) AP35(6.247,-0.28) AP37(6.247,0.634) AP38(6.247,1.548) AP40(6.247,2.463) AP42(6.247,3.377) AP43(6.247,4.292) AP45(6.247,5.206) AP46(6.247,6.12) AP48(6.247,7.035) AP50(6.247,7.949) AP52(6.247,8.864) AP53(6.247,9.778) AP55(6.247,10.692) AP56(6.247,11.607) AP58(6.247,12.521) AP60(6.247,13.436) AP61(6.247,14.35) AP63(6.247,15.264) AP65(6.247,16.179) AP66(6.247,17.093) AP68(6.332,18.039) AP70(6.332,19.258) AR5(6.897,-17.654) AR7(6.897,-16.74) AR8(6.897,-15.825) AR10(6.897,-14.911) AR11(6.897,-13.996) AR13(6.897,-13.082) AR15(6.897,-12.168) AR16(6.897,-11.253) AR18(6.897,-10.339) AR20(6.897,-9.424) AR21(6.897,-8.51) AR22(6.897,-7.596) AR23(6.897,-6.681) AR25(6.897,-5.767) AR27(6.897,-4.852) AR28(6.897,-3.938) AR30(6.897,-3.024) AR32(6.897,-2.109) AR33(6.897,-1.195) AR35(6.897,-0.28) AR37(6.897,0.634) AR38(6.897,1.548) AR40(6.897,2.463) AR42(6.897,3.377) AR43(6.897,4.292) AR45(6.897,5.206) AR46(6.897,6.12) AR48(6.897,7.035) AR50(6.897,7.949) AR52(6.897,8.864) AR53(6.897,9.778) AR55(6.897,10.692) AR56(6.897,11.607) AR58(6.897,12.521) AR60(6.897,13.436) AR61(6.897,14.35) AR63(6.897,15.264) AR65(6.897,16.179) AR66(6.897,17.093) AR68(6.945,18.364) AR69(6.945,19.014) AT2(7.445,-19.339) AT4(7.445,-18.363) AT5(7.547,-17.654) AT7(7.547,-16.74) AT8(7.547,-15.825) AT10(7.547,-14.911) AT11(7.547,-13.996) AT13(7.547,-13.082) AT15(7.547,-12.168) AT16(7.547,-11.253) AT18(7.547,-10.339) AT20(7.547,-9.424) AT21(7.547,-8.51) AT22(7.547,-7.596) AT23(7.547,-6.681) AT25(7.547,-5.767) AT27(7.547,-4.852) AT28(7.547,-3.938) AT30(7.547,-3.024) AT32(7.547,-2.109) AT33(7.547,-1.195) AT35(7.547,-0.28) AT37(7.547,0.634) AT38(7.547,1.548) AT40(7.547,2.463) AT42(7.547,3.377) AT43(7.547,4.292) AT45(7.547,5.206) AT46(7.547,6.12) AT48(7.547,7.035) AT50(7.547,7.949) AT52(7.547,8.864) AT53(7.547,9.778) AT55(7.547,10.692) AT56(7.547,11.607) AT58(7.547,12.521) AT60(7.547,13.436) AT61(7.547,14.35) AT63(7.547,15.264) AT65(7.547,16.179) AT66(7.547,17.093) AT68(7.509,18.039) AT69(7.509,18.689) AU4(8.108,-18.363) AU5(8.198,-17.654) AU7(8.198,-16.74) AU8(8.198,-15.825) AU10(8.198,-14.911) AU11(8.198,-13.996) AU13(8.198,-13.082) AU15(8.198,-12.168) AU16(8.198,-11.253) AU18(8.198,-10.339) AU20(8.198,-9.424) AU21(8.198,-8.51) AU22(8.198,-7.596) AU23(8.198,-6.681) AU25(8.198,-5.767) AU27(8.198,-4.852) AU28(8.198,-3.938) AU30(8.198,-3.024) AU32(8.198,-2.109) AU33(8.198,-1.195) AU35(8.198,-0.28) AU37(8.198,0.634) AU38(8.198,1.548) AU40(8.198,2.463) AU42(8.198,3.377) AU43(8.198,4.292) AU45(8.198,5.206) AU46(8.198,6.12) AU48(8.198,7.035) AU50(8.198,7.949) AU52(8.198,8.864) AU53(8.198,9.778) AU55(8.198,10.692) AU56(8.198,11.607) AU58(8.198,12.521) AU60(8.198,13.436) AU61(8.198,14.35) AU63(8.198,15.264) AU65(8.198,16.179) AU66(8.198,17.093) AV3(8.799,-18.689) AV68(8.711,18.029) AV69(8.901,19.014) AV70(8.901,19.664) AW1(9.551,-20.314) AW5(8.911,-17.781) AW6(9.038,-17.13) AW7(9.363,-16.564) AW8(9.038,-15.986) AW9(9.363,-15.416) AW10(9.038,-14.753) AW11(9.363,-14.143) AW12(9.038,-13.565) AW13(9.363,-12.995) AW14(9.038,-12.332) AW15(9.363,-11.723) AW16(9.038,-11.145) AW17(9.363,-10.575) AW18(9.038,-9.912) AW20(9.363,-9.302) AW21(9.038,-8.724) AW22(9.363,-8.154) AW23(9.038,-7.466) AW25(9.363,-6.828) AW26(9.038,-6.264) AW27(9.363,-5.601) AW28(9.038,-4.988) AW29(9.363,-4.374) AW30(9.038,-3.711) AW31(9.363,-3.148) AW32(9.038,-2.485) AW33(9.363,-1.847) AW34(9.038,-1.283) AW35(9.363,-0.62) AW36(9.038,-0.007) AW37(9.363,0.607) AW38(9.038,1.269) AW39(9.363,1.833) AW41(9.038,2.471) AW42(9.363,3.108) AW43(9.038,3.672) AW44(9.363,4.335) AW45(9.038,4.949) AW46(9.363,5.562) AW47(9.038,6.163) AW48(9.363,6.727) AW49(9.038,7.355) AW50(9.363,7.984) AW51(9.038,8.548) AW52(9.363,9.149) AW53(9.038,9.762) AW54(9.363,10.375) AW55(9.038,11.038) AW56(9.363,11.602) AW57(9.038,12.24) AW59(9.363,12.877) AW60(9.038,13.441) AW61(9.363,14.104) AW62(9.038,14.718) AW63(9.363,15.331) AW64(9.038,15.994) AW65(9.363,16.558) AW66(8.9,17.093) AW67(9.371,18.018) AW68(9.622,18.622) AW69(9.536,19.267) AW70(10.035,19.685) AW71(9.551,20.314) AY2(10.034,-19.685) AY3(10.028,-19.028) AY4(10.043,-18.274) AY5(9.689,-17.665) AY8(9.689,-15.986) AY12(9.689,-13.565) AY16(9.689,-11.145) AY21(9.689,-8.724) AY26(9.689,-6.264) AY27(10.014,-5.601) AY29(10.014,-4.374) AY30(9.689,-3.711) AY34(9.689,-1.283) AY35(10.014,-0.62) AY37(10.014,0.607) AY38(9.689,1.269) AY43(9.689,3.672) AY44(10.014,4.335) AY46(10.014,5.562) AY47(9.689,6.163) AY51(9.689,8.548) AY52(10.014,9.149) AY54(10.014,10.375) AY55(9.689,11.038) AY60(9.689,13.441) AY61(10.014,14.104) AY63(10.014,15.331) AY64(9.689,15.994) AY66(9.689,17.221) AY68(10.267,18.535) B5(-10.664,-18.048) B6(-10.339,-17.467) B10(-10.339,-14.989) B14(-10.339,-12.511) B18(-10.339,-10.033) B22(-10.339,-7.555) B26(-10.339,-5.077) B30(-10.339,-2.599) B34(-10.339,-0.121) B39(-10.339,2.357) B44(-10.339,4.835) B48(-10.339,7.313) B53(-10.339,9.791) B58(-10.339,12.269) B62(-10.339,14.747) B66(-10.339,17.226) B69(-10.685,19.035) BA3(10.685,-19.035) BA5(10.626,-17.715) BA8(10.339,-15.986) BA12(10.339,-13.565) BA16(10.339,-11.145) BA21(10.339,-8.724) BA23(10.258,-7.466) BA28(10.258,-4.988) BA32(10.258,-2.485) BA36(10.258,-0.007) BA41(10.258,2.471) BA45(10.258,4.949) BA49(10.339,7.355) BA53(10.258,9.762) BA57(10.258,12.24) BA62(10.258,14.718) BA68(10.685,19.035) BB4(11.314,-18.551) BB68(11.314,18.552) C4(-10.336,-18.615) C5(-10.014,-18.048) C7(-10.014,-16.791) C8(-10.339,-16.228) C9(-10.014,-15.664) C11(-10.014,-14.313) C12(-10.339,-13.75) C13(-10.014,-13.186) C15(-10.014,-11.835) C16(-10.339,-11.272) C17(-10.014,-10.708) C19(-10.014,-9.357) C20(-10.339,-8.794) C21(-10.014,-8.23) C23(-10.014,-6.879) C24(-10.339,-6.316) C25(-10.014,-5.752) C27(-10.014,-4.401) C28(-10.339,-3.838) C29(-10.014,-3.274) C31(-10.014,-1.923) C32(-10.339,-1.36) C33(-10.014,-0.796) C36(-10.014,0.555) C37(-10.339,1.118) C38(-10.014,1.682) C40(-10.014,3.033) C41(-10.339,3.596) C42(-10.014,4.16) C45(-10.014,5.511) C46(-10.339,6.074) C47(-10.014,6.638) C50(-10.014,7.989) C51(-10.339,8.552) C52(-10.014,9.116) C54(-10.014,10.467) C55(-10.339,11.03) C56(-10.014,11.594) C59(-10.014,12.945) C60(-10.339,13.508) C61(-10.014,14.072) C63(-10.014,15.423) C64(-10.339,15.987) C65(-10.014,16.55) C67(-10.299,18.485) C68(-9.622,18.622) C70(-10.034,19.685) D3(-9.608,-19.339) D4(-9.669,-18.691) D5(-9.363,-18.09) D6(-9.323,-17.441) D7(-9.363,-16.791) D8(-9.689,-16.228) D9(-9.363,-15.664) D10(-9.323,-14.989) D11(-9.363,-14.313) D12(-9.689,-13.75) D13(-9.363,-13.186) D14(-9.323,-12.511) D15(-9.363,-11.835) D16(-9.689,-11.272) D17(-9.363,-10.708) D18(-9.323,-10.033) D19(-9.363,-9.357) D20(-9.689,-8.794) D21(-9.363,-8.23) D22(-9.323,-7.555) D23(-9.363,-6.879) D24(-9.689,-6.316) D25(-9.363,-5.752) D26(-9.323,-5.077) D27(-9.363,-4.401) D28(-9.689,-3.838) D29(-9.363,-3.274) D30(-9.323,-2.599) D31(-9.363,-1.923) D32(-9.689,-1.36) D33(-9.363,-0.796) D34(-9.323,-0.121) D36(-9.363,0.555) D37(-9.689,1.118) D38(-9.363,1.682) D39(-9.323,2.357) D40(-9.363,3.033) D41(-9.689,3.596) D42(-9.363,4.16) D44(-9.323,4.835) D45(-9.363,5.511) D46(-9.689,6.074) D47(-9.363,6.638) D48(-9.323,7.313) D50(-9.363,7.989) D51(-9.689,8.552) D52(-9.363,9.116) D53(-9.323,9.791) D54(-9.363,10.467) D55(-9.689,11.03) D56(-9.363,11.594) D58(-9.323,12.269) D59(-9.363,12.945) D60(-9.689,13.508) D61(-9.363,14.072) D62(-9.323,14.747) D63(-9.363,15.423) D64(-9.689,15.987) D65(-9.363,16.55) D66(-9.323,17.226) D67(-10.014,17.899) D68(-9.535,19.267) D69(-8.971,18.562) D71(-9.551,20.314) E1(-9.04,-20.314) E2(-9.04,-19.664) E3(-9.04,-19.014) E5(-8.591,-17.654) E6(-8.591,-16.74) E8(-8.591,-15.825) E10(-8.591,-14.911) E11(-8.591,-13.996) E13(-8.591,-13.082) E15(-8.591,-12.168) E16(-8.591,-11.253) E18(-8.591,-10.339) E20(-8.591,-9.424) E21(-8.591,-8.51) E22(-8.591,-7.596) E23(-8.591,-6.681) E25(-8.591,-5.767) E27(-8.591,-4.852) E28(-8.591,-3.938) E30(-8.591,-3.024) E32(-8.591,-2.109) E33(-8.591,-1.195) E35(-8.591,-0.28) E37(-8.591,0.634) E38(-8.591,1.548) E40(-8.591,2.463) E42(-8.591,3.377) E43(-8.591,4.292) E45(-8.591,5.206) E46(-8.591,6.12) E48(-8.591,7.035) E50(-8.591,7.949) E52(-8.591,8.864) E53(-8.591,9.778) E55(-8.591,10.692) E56(-8.591,11.607) E58(-8.591,12.521) E60(-8.591,13.436) E61(-8.591,14.35) E63(-8.655,15.315) E65(-8.655,16.331) E66(-8.655,17.347) E68(-9.363,17.899) F2(-8.466,-19.339) F4(-8.466,-18.363) F5(-7.941,-17.654) F6(-7.941,-16.74) F8(-7.941,-15.825) F10(-7.941,-14.911) F11(-7.941,-13.996) F13(-7.941,-13.082) F15(-7.941,-12.168) F16(-7.941,-11.253) F18(-7.941,-10.339) F20(-7.941,-9.424) F21(-7.941,-8.51) F22(-7.941,-7.596) F23(-7.941,-6.681) F25(-7.941,-5.767) F27(-7.941,-4.852) F28(-7.941,-3.938) F30(-7.941,-3.024) F32(-7.941,-2.109) F33(-7.941,-1.195) F35(-7.941,-0.28) F37(-7.941,0.634) F38(-7.941,1.548) F40(-7.941,2.463) F42(-7.941,3.377) F43(-7.941,4.292) F45(-7.941,5.206) F46(-7.941,6.12) F48(-7.941,7.035) F50(-7.941,7.949) F52(-7.941,8.864) F53(-7.941,9.778) F55(-7.941,10.692) F56(-7.941,11.607) F58(-7.941,12.521) F60(-7.941,13.436) F61(-7.941,14.35) F63(-8.005,15.315) F65(-8.005,16.331) F66(-8.005,17.347) F68(-8.32,18.562) G4(-7.803,-18.363) G5(-7.291,-17.654) G6(-7.291,-16.74) G8(-7.291,-15.825) G10(-7.291,-14.911) G11(-7.291,-13.996) G13(-7.291,-13.082) G15(-7.291,-12.168) G16(-7.291,-11.253) G18(-7.291,-10.339) G20(-7.291,-9.424) G21(-7.291,-8.51) G22(-7.291,-7.596) G23(-7.291,-6.681) G25(-7.291,-5.767) G27(-7.291,-4.852) G28(-7.291,-3.938) G30(-7.291,-3.024) G32(-7.291,-2.109) G33(-7.291,-1.195) G35(-7.291,-0.28) G37(-7.291,0.634) G38(-7.291,1.548) G40(-7.291,2.463) G42(-7.291,3.377) G43(-7.291,4.292) G45(-7.291,5.206) G46(-7.291,6.12) G48(-7.291,7.035) G50(-7.291,7.949) G52(-7.291,8.864) G53(-7.291,9.778) G55(-7.291,10.692) G56(-7.291,11.607) G58(-7.291,12.521) G60(-7.291,13.436) G61(-7.291,14.35) G63(-7.354,15.315) G65(-7.354,16.331) G66(-7.354,17.347) G68(-7.66,18.364) G69(-7.66,19.014) H3(-7.14,-18.689) H5(-6.641,-17.654) H6(-6.641,-16.74) H8(-6.641,-15.825) H10(-6.641,-14.911) H11(-6.641,-13.996) H13(-6.641,-13.082) H15(-6.641,-12.168) H16(-6.641,-11.253) H18(-6.641,-10.339) H20(-6.641,-9.424) H21(-6.641,-8.51) H63(-6.704,15.315) H65(-6.704,16.331) H66(-6.704,17.347) H69(-7.096,18.689) J4(-6.477,-18.363) J5(-5.99,-17.654) J6(-5.99,-16.74) J8(-5.99,-15.825) J10(-5.99,-14.911) J11(-5.99,-13.996) J13(-5.99,-13.082) J22(-6.827,-7.138) J23(-6.827,-6.224) J25(-6.827,-5.31) J27(-6.827,-4.395) J28(-6.827,-3.481) J30(-6.827,-2.566) J32(-6.827,-1.652) J33(-6.827,-0.738) J35(-6.827,0.177) J37(-6.827,1.091) J38(-6.827,2.006) J40(-6.827,2.92) J42(-6.827,3.834) J43(-6.827,4.749) J45(-6.827,5.663) J46(-6.827,6.578) J48(-6.827,7.492) J50(-6.827,8.406) J52(-6.827,9.321) J53(-6.827,10.235) J55(-6.827,11.15) J56(-6.827,12.064) J58(-6.827,12.978) J60(-6.827,13.893) J68(-6.52,18.362) K15(-5.876,-12.188) K16(-5.876,-11.538) K17(-5.876,-10.888) K18(-5.876,-10.237) K19(-5.876,-9.587) K20(-5.876,-8.937) K21(-5.876,-8.287) K22(-6.362,-7.596) K23(-6.362,-6.681) K25(-6.362,-5.767) K27(-6.362,-4.852) K28(-6.362,-3.938) K30(-6.362,-3.024) K32(-6.362,-2.109) K33(-6.362,-1.195) K35(-6.362,-0.28) K37(-6.362,0.634) K38(-6.362,1.548) K40(-6.362,2.463) K42(-6.362,3.377) K43(-6.362,4.292) K45(-6.362,5.206) K46(-6.362,6.12) K48(-6.362,7.035) K50(-6.362,7.949) K52(-6.362,8.864) K53(-6.362,9.778) K55(-6.362,10.692) K56(-6.362,11.607) K58(-6.362,12.521) K60(-6.362,13.436) K61(-6.362,14.35) K63(-6.054,15.133) K64(-6.054,15.783) K65(-6.054,16.433) K66(-6.054,17.084) K67(-6.054,17.734) K68(-5.846,18.352) K70(-5.744,19.339) L2(-5.814,-19.339) L4(-5.814,-18.363) L6(-5.34,-17.585) L7(-5.34,-16.935) L8(-5.34,-16.285) L9(-5.34,-15.635) L10(-5.34,-14.984) L11(-5.34,-14.334) L12(-5.34,-13.684) L13(-5.34,-13.034) L15(-5.038,-12.188) L16(-5.038,-11.538) L17(-5.038,-10.888) L18(-5.038,-10.237) L19(-5.038,-9.587) L20(-5.038,-8.937) L21(-5.038,-8.287) L62(-5.625,14.644) L63(-5.168,15.112) L64(-5.168,15.763) L65(-5.168,16.413) L66(-5.168,17.063) L67(-5.168,17.713) L68(-5.168,18.364) L69(-5.168,19.014) L70(-5.168,19.664) L71(-5.168,20.314) M4(-5.151,-18.363) M62(-4.71,14.644) N3(-4.488,-18.689) N6(-4.4,-17.585) N7(-4.4,-16.935) N8(-4.4,-16.285) N9(-4.4,-15.635) N10(-4.4,-14.984) N11(-4.4,-14.334) N12(-4.4,-13.684) N13(-4.4,-13.034) N15(-4.2,-12.188) N16(-4.2,-11.538) N17(-4.2,-10.888) N18(-4.2,-10.237) N19(-4.2,-9.587) N20(-4.2,-8.937) N21(-4.2,-8.287) N63(-4.253,15.112) N64(-4.253,15.763) N65(-4.253,16.413) N66(-4.253,17.063) N67(-4.253,17.713) N68(-4.253,18.364) N69(-4.253,19.014) N70(-4.253,19.664) N71(-4.253,20.314) P4(-3.825,-18.363) P15(-3.362,-12.188) P16(-3.362,-11.538) P17(-3.362,-10.888) P18(-3.362,-10.237) P19(-3.362,-9.587) P20(-3.362,-8.937) P21(-3.362,-8.287) P62(-3.796,14.644) R6(-3.333,-17.585) R7(-3.333,-16.935) R8(-3.333,-16.285) R9(-3.333,-15.635) R10(-3.333,-14.984) R11(-3.333,-14.334) R12(-3.333,-13.684) R13(-3.333,-13.034) R63(-3.339,15.112) R64(-3.339,15.763) R65(-3.339,16.413) R66(-3.339,17.063) R67(-3.339,17.713) R68(-3.339,18.364) R69(-3.339,19.014) R70(-3.339,19.664) R71(-3.339,20.314) T2(-3.162,-19.339) T4(-3.162,-18.363) T15(-2.523,-12.188) T16(-2.523,-11.538) T17(-2.523,-10.888) T18(-2.523,-10.237) T19(-2.523,-9.587) T20(-2.523,-8.937) T21(-2.523,-8.287) T62(-2.882,14.644) U4(-2.499,-18.363) U6(-2.267,-17.585) U7(-2.267,-16.935) U8(-2.267,-16.285) U9(-2.267,-15.635) U10(-2.267,-14.984) U11(-2.267,-14.334) U12(-2.267,-13.684) U13(-2.267,-13.034) U63(-2.424,15.112) U64(-2.424,15.763) U65(-2.424,16.413) U66(-2.424,17.063) U67(-2.424,17.713) U68(-2.424,18.364) U69(-2.424,19.014) U70(-2.424,19.664) U71(-2.424,20.314) V3(-1.836,-18.689) V15(-1.685,-12.188) V16(-1.685,-11.538) V17(-1.685,-10.888) V18(-1.685,-10.237) V19(-1.685,-9.587) V20(-1.685,-8.937) V21(-1.685,-8.287) V62(-1.967,14.644) W4(-1.173,-18.363) W6(-1.2,-17.585) W7(-1.2,-16.935) W8(-1.2,-16.285) W9(-1.2,-15.635) W10(-1.2,-14.984) W11(-1.2,-14.334) W12(-1.2,-13.684) W13(-1.2,-13.034) W63(-1.51,15.112) W64(-1.51,15.763) W65(-1.51,16.413) W66(-1.51,17.063) W67(-1.51,17.713) W68(-1.51,18.364) W69(-1.51,19.014) W70(-1.51,19.664) W71(-1.51,20.314) Y15(-0.847,-12.188) Y16(-0.847,-11.538) Y17(-0.847,-10.888) Y18(-0.847,-10.237) Y19(-0.847,-9.587) Y20(-0.847,-8.937) Y21(-0.847,-8.287) Y62(-1.053,14.644)
  oval 0.343x0.254 smd: A6(-10.989,-17.467) A7(-11.314,-16.791) A9(-11.314,-15.664) A10(-10.989,-14.989) A11(-11.314,-14.313) A13(-11.314,-13.186) A14(-10.989,-12.511) A15(-11.314,-11.835) A17(-11.314,-10.708) A18(-10.989,-10.033) A19(-11.314,-9.357) A21(-11.314,-8.23) A22(-10.989,-7.555) A23(-11.314,-6.879) A25(-11.314,-5.752) A26(-10.989,-5.077) A27(-11.314,-4.401) A29(-11.314,-3.274) A30(-10.989,-2.599) A31(-11.314,-1.923) A33(-11.314,-0.796) A34(-10.989,-0.121) A36(-11.314,0.555) A38(-11.314,1.682) A39(-10.989,2.357) A40(-11.314,3.033) A42(-11.314,4.16) A44(-10.989,4.835) A45(-11.314,5.511) A47(-11.314,6.638) A48(-10.989,7.313) A50(-11.314,7.989) A52(-11.314,9.116) A53(-10.989,9.791) A54(-11.314,10.467) A56(-11.314,11.594) A58(-10.989,12.269) A59(-11.314,12.945) A61(-11.314,14.072) A62(-10.989,14.747) A63(-11.314,15.423) A65(-11.314,16.55) A66(-10.989,17.226) A67(-11.314,17.901) AY7(10.014,-16.551) AY9(10.014,-15.416) AY11(10.014,-14.13) AY13(10.014,-12.995) AY15(10.014,-11.71) AY17(10.014,-10.574) AY20(10.014,-9.289) AY22(10.014,-8.154) AY25(10.014,-6.828) AY31(10.014,-3.148) AY33(10.014,-1.847) AY39(10.014,1.834) AY42(10.014,3.109) AY48(10.014,6.789) AY50(10.014,7.922) AY56(10.014,11.602) AY59(10.014,12.877) AY65(10.014,16.558) AY67(10.014,17.901) B7(-10.664,-16.791) B9(-10.664,-15.664) B11(-10.664,-14.313) B13(-10.664,-13.186) B15(-10.664,-11.835) B17(-10.664,-10.708) B19(-10.664,-9.357) B21(-10.664,-8.23) B23(-10.664,-6.879) B25(-10.664,-5.752) B27(-10.664,-4.401) B29(-10.664,-3.274) B31(-10.664,-1.923) B33(-10.664,-0.796) B36(-10.664,0.555) B38(-10.664,1.682) B40(-10.664,3.033) B42(-10.664,4.16) B45(-10.664,5.511) B47(-10.664,6.638) B50(-10.664,7.989) B52(-10.664,9.116) B54(-10.664,10.467) B56(-10.664,11.594) B59(-10.664,12.945) B61(-10.664,14.072) B63(-10.664,15.423) B65(-10.664,16.55) B67(-10.664,17.901) BA4(10.689,-18.366) BA6(10.257,-17.173) BA7(10.664,-16.61) BA9(10.664,-15.416) BA10(10.257,-14.753) BA11(10.664,-14.189) BA13(10.664,-12.995) BA14(10.257,-12.332) BA15(10.664,-11.768) BA17(10.664,-10.574) BA18(10.257,-9.912) BA20(10.664,-9.348) BA22(10.664,-8.154) BA25(10.664,-6.828) BA26(10.339,-6.165) BA27(10.664,-5.502) BA29(10.664,-4.473) BA30(10.339,-3.811) BA31(10.664,-3.148) BA33(10.664,-1.847) BA34(10.339,-1.184) BA35(10.664,-0.521) BA37(10.664,0.507) BA38(10.339,1.17) BA39(10.664,1.834) BA42(10.664,3.109) BA43(10.339,3.771) BA44(10.664,4.434) BA46(10.664,5.463) BA47(10.339,6.126) BA48(10.664,6.789) BA50(10.664,7.922) BA51(10.339,8.585) BA52(10.664,9.248) BA54(10.664,10.276) BA55(10.339,10.939) BA56(10.664,11.602) BA59(10.664,12.877) BA60(10.339,13.54) BA61(10.664,14.203) BA63(10.664,15.232) BA64(10.339,15.895) BA65(10.664,16.558) BA66(10.339,17.221) BA67(10.664,17.901) BB5(11.314,-17.786) BB6(10.989,-17.173) BB7(11.314,-16.61) BB9(11.314,-15.416) BB10(10.989,-14.753) BB11(11.314,-14.189) BB13(11.314,-12.995) BB14(10.989,-12.332) BB15(11.314,-11.768) BB17(11.314,-10.574) BB18(10.989,-9.912) BB20(11.314,-9.348) BB22(11.314,-8.154) BB23(10.908,-7.466) BB25(11.314,-6.828) BB26(10.989,-6.165) BB27(11.314,-5.502) BB29(11.314,-4.473) BB30(10.989,-3.811) BB31(11.314,-3.148) BB32(10.908,-2.484) BB33(11.314,-1.847) BB34(10.989,-1.184) BB35(11.314,-0.521) BB37(11.314,0.507) BB38(10.989,1.17) BB39(11.314,1.834) BB41(10.908,2.471) BB42(11.314,3.109) BB43(10.989,3.771) BB44(11.314,4.434) BB46(11.314,5.463) BB47(10.989,6.126) BB48(11.314,6.789) BB50(11.314,7.922) BB51(10.989,8.585) BB52(11.314,9.248) BB54(11.314,10.276) BB55(10.989,10.939) BB56(11.314,11.602) BB57(10.908,12.24) BB59(11.314,12.877) BB60(10.989,13.54) BB61(11.314,14.203) BB63(11.314,15.232) BB64(10.989,15.895) BB65(11.314,16.558) BB66(10.989,17.221) BB67(11.314,17.901)
  oval 0.254x0.343 smd: AA1(-0.51,-19.989) AB1(0.153,-20.314) AB2(0.153,-19.664) AB3(0.153,-19.013) AC1(0.815,-19.989) AC2(0.815,-19.339) AD1(1.479,-20.314) AD2(1.479,-19.664) AD3(1.479,-19.013) AF1(2.141,-19.989) AF70(1.84,19.664) AF71(1.84,20.314) AG1(2.804,-20.314) AG2(2.804,-19.664) AG3(2.804,-19.013) AG70(2.503,19.339) AG71(2.503,19.989) AH1(3.467,-19.989) AH2(3.467,-19.339) AH68(3.166,18.363) AH69(3.166,19.014) AH70(3.166,19.664) AH71(3.166,20.314) AJ1(4.13,-20.314) AJ2(4.13,-19.664) AJ3(4.13,-19.013) AK70(3.829,19.989) AL1(4.793,-19.989) AL68(4.492,18.363) AL69(4.492,19.014) AL70(4.492,19.664) AL71(4.492,20.314) AM1(5.456,-20.314) AM2(5.456,-19.664) AM3(5.456,-19.013) AM70(5.155,19.339) AM71(5.155,19.989) AN1(6.119,-19.989) AN2(6.119,-19.339) AN70(5.818,19.664) AN71(5.818,20.314) AP1(6.782,-20.314) AP2(6.782,-19.664) AP3(6.782,-19.013) AR70(6.846,19.664) AR71(6.846,20.314) AT1(7.445,-19.989) AT70(7.509,19.339) AT71(7.509,19.989) AU1(8.108,-20.314) AU2(8.108,-19.664) AU3(8.108,-19.013) AU68(8.147,18.363) AU69(8.172,19.014) AU70(8.172,19.664) AU71(8.172,20.314) AV1(8.828,-20.314) AV2(8.799,-19.364) AV71(8.901,20.314) AW2(9.363,-19.689) AW3(9.363,-19.039) E70(-9.009,19.664) E71(-8.901,20.314) F1(-8.466,-19.989) F70(-8.32,19.212) F71(-8.384,19.862) G1(-7.803,-20.314) G2(-7.803,-19.664) G3(-7.803,-19.013) G70(-7.759,19.664) G71(-7.759,20.314) H1(-7.14,-19.989) H2(-7.14,-19.339) H70(-7.096,19.339) H71(-7.096,19.989) J1(-6.477,-20.314) J2(-6.477,-19.664) J3(-6.477,-19.013) J69(-6.433,19.014) J70(-6.433,19.664) J71(-6.433,20.314) K71(-5.744,19.989) L1(-5.814,-19.989) M1(-5.151,-20.314) M2(-5.151,-19.664) M3(-5.151,-19.013) N1(-4.488,-19.989) N2(-4.488,-19.339) P1(-3.825,-20.314) P2(-3.825,-19.664) P3(-3.825,-19.013) T1(-3.162,-19.989) U1(-2.499,-20.314) U2(-2.499,-19.664) U3(-2.499,-19.013) V1(-1.836,-19.989) V2(-1.836,-19.339) W1(-1.173,-20.314) W2(-1.173,-19.664) W3(-1.173,-19.013)
C0201
  rect 0.203x0.381 smd: 1(-0.225,0) 2(0.225,0)
C0402
  custom 0.12x0.12 smd: 1(0.39,0) 2(-0.39,0)
C0402_2
  custom 0.12x0.12 smd: 1(0.39,0) 2(-0.39,0)
C0603
  rect 0.686x0.813 smd: 1(0.6,0) 2(-0.6,0)
C0805
  rect 0.864x1.372 smd: 1(0.88,0) 2(-0.88,0)
C3528
  rect 1.6x2.591 smd: 1(1.5,0) 2(-1.5,0)
CC7343
  rect 2.413x2.819 smd: 1(-3.2,0) 2(3.2,0)
CHOKE-DLP11SN900HL2L-4P-1
  rect 0.711x0.305 smd: 1(-0.625,0.275) 2(0.625,0.275) 3(0.625,-0.275) 4(-0.625,-0.275)
CHOKE-DLW21S-4P
  rect 0.889x0.356 smd: 1(-0.85,0.425) 2(0.85,0.425) 3(0.85,-0.425) 4(-0.85,-0.425)
CHOKE-PCMC063T-3R3MN-SMT
  rect 1.854x3.505 smd: 1(-3.275,0) 2(3.275,0)
D-1X0_6-D24V0L1B2LPS
  rect 0.457x0.61 smd: 1(-0.375,0) 2(0.375,0)
D-3_8X2_5
  rect 1.6x1.905 smd: 1(-2.15,0) 2(2.15,0)
DFN8-2X2-5-9P-ISL6208BCRZ
  rect 0.229x0.508 smd: 1(-0.75,-0.95) 2(-0.25,-0.95) 3(0.25,-0.95) 4(0.75,-0.95) 5(0.75,0.95) 6(0.25,0.95) 7(-0.25,0.95) 8(-0.75,0.95)
  rect 1.549x0.889 smd: 9(0,0)
DFN10-4_1X2-8-11P
  rect 0.203x0.61 smd: 1(-1.8,-0.9) 2(-1,-0.9) 3(-0.2,-0.9) 4(0.6,-0.9) 5(1.4,-0.9) 6(1.8,0.9) 7(1,0.9) 8(0.2,0.9) 9(-0.6,0.9) 10(-1.4,0.9)
  rect 1.397x0.787 smd: 11(-0.4,0)
DFN2018-6-1_8X2-5-7P
  rect 0.356x0.254 smd: 1(0.975,-0.5) 2(0.975,0) 3(0.975,0.5) 4(-0.975,0.5) 5(-0.975,0) 6(-0.975,-0.5)
  rect 1.194x1.6 smd: 7(0,0)
DSM
  rect 1.016x0.508 smd: 1(-1.3,0) 2(1.321,0)
ESD-1X0_6-2P
  rect 0.559x0.61 smd: 1(-0.425,0) 2(0.425,0)
FILTER-MCM2012B900GBE-4P
  rect 0.762x0.406 smd: 1(-0.925,0.4) 2(0.925,0.4) 3(0.925,-0.4) 4(-0.925,-0.4)
H-C98D98N
  round 2.489 hole 2.489 unplated: (0,0)
H-C197D197N
  round 5.004 hole 5.004 unplated: (0,0)
H-TC197IC182D142PT
  round 5.004 hole 3.607: 1(0,0)
H-TC220IC186D146PT
  round 5.588 hole 3.708: 1(0,0)
H-TIC221BC236D142P2
  round 5.994 hole 3.607: 1(0,0)
H-ZHD-1
  custom 0.66x0.66 smd: 1(-1.448,1.448) 2(1.448,1.448) 3(1.448,-1.448) 4(-1.448,-1.448)
  round 7.595 hole 2.489: 5(0,0)
H-ZHD-2
  custom 1.705x1.705 hole 5.512: 1(0,0)
HDMI-59058-0190D-001-19P-SMT
  round 0.813 hole 0.559: 1(-4.5,6.08) 2(-4,7.58) 3(-3.5,6.08) 4(-3,7.58) 5(-2.5,6.08) 6(-2,7.58) 7(-1.5,6.08) 8(-1,7.58) 9(-0.5,6.08) 10(0,7.58) 11(0.5,6.08) 12(1,7.58) 13(1.5,6.08) 14(2,7.58) 15(2.5,6.08) 16(3,7.58) 17(3.5,6.08) 18(4,7.58) 19(4.5,6.08)
  oval 1.803x2.794 hole 0.787x1.803: 20(-9.25,0) 22(9.25,0)
  oval 1.397x3.15 hole 0.787x2.54: 21(-7.25,6.98) 23(7.25,6.98)
HG-C236D98P2
  round 5.994 hole 2.489: 1(0,0)
  round 1.016 hole 0.61: 2(0,2.121) 3(1.5,1.5) 4(2.121,0) 5(1.5,-1.5) 6(0,-2.121) 7(-1.5,-1.5) 8(-2.121,0) 9(-1.5,1.5)
HG-C299D98P2
  round 7.595 hole 2.489: 1(0,0)
  round 0.61 hole 0.356: 2(0,2.197) 3(1.553,1.553) 4(2.197,0) 5(1.553,-1.553) 6(0,-2.197) 7(-1.553,-1.553) 8(-2.197,0) 9(-1.553,1.553)
HG-C299D158P2
  round 7.595 hole 4.013: 1(0,0)
  round 0.61 hole 0.356: 2(0,2.794) 3(1.976,1.976) 4(2.794,0) 5(1.976,-1.976) 6(0,-2.794) 7(-1.976,-1.976) 8(-2.794,0) 9(-1.976,1.976)
